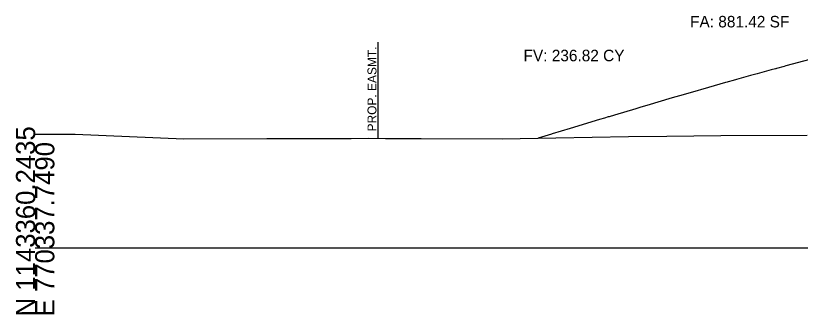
# Model space of a CAD drawing. Extents: x -26 to 5403, y -13 to 9553.
# Drawn here: x 3997.2 to 4111.7, y 1990.3 to 2033.8 of the extents above; entities that cross this region are included whole.
import ezdxf

# ---------------------------------------------------------------- set-up
doc = ezdxf.new("R2010")
doc.units = 0
for name, color, linetype in [('Draft_XS_Grid', 7, 'Continuous'), ('DTM_X_GROUND', 7, 'Continuous'), ('ROW_EASEMENTS', 7, 'Continuous'), ('SLOPE_STAKES_FILL', 7, 'Continuous'), ('XS_CELL', 7, 'Continuous'), ('XS_M_SHAPES_EARTHWORK', 7, 'Continuous'), ('XS_P_GROUND', 7, 'Continuous'), ('XS_SHEET_EW_TX_AREA', 7, 'Continuous'), ('XS_SHEET_EW_TX_VOLUME', 7, 'Continuous')]:
    doc.layers.add(name, color=color, linetype=linetype)

msp = doc.modelspace()

# ---------------------------------------------------------------- linework, layer by layer
at = {"layer": 'DTM_X_GROUND'}
msp.add_lwpolyline([(4000, 2016.56), (4005.83, 2016.53), (4021.71, 2015.84), (4033.8, 2015.93), (4036.66, 2015.9), (4046.12, 2015.93), (4048.71, 2015.94), (4051.11, 2015.93), (4056.33, 2015.92), (4068.17, 2015.87), (4075.98, 2015.99), (4086.57, 2016.19), (4092.16, 2016.23), (4100.06, 2016.35), (4112.65, 2016.39)], dxfattribs=at)
at = {"layer": 'ROW_EASEMENTS'}
msp.add_line((4050, 2029.94), (4050, 2015.94), dxfattribs=at)
at = {"layer": 'XS_CELL'}
msp.add_line((4000, 2000), (4200, 2000), dxfattribs=at)
at = {"layer": 'XS_M_SHAPES_EARTHWORK'}
msp.add_lwpolyline([(4113.03, 2027.41), (4109.54, 2026.48), (4109.28, 2026.41), (4108.2, 2026.11), (4108.07, 2026.08), (4108.03, 2026.07), (4107.38, 2025.9), (4105.37, 2025.34), (4104.39, 2025.07), (4102.35, 2024.5), (4101.87, 2024.37), (4101.14, 2024.17), (4100.98, 2024.12), (4100.76, 2024.06), (4098.28, 2023.36), (4095.59, 2022.58), (4094.04, 2022.14), (4092.96, 2021.82), (4090.85, 2021.21), (4089.76, 2020.88), (4088.24, 2020.43), (4087.64, 2020.25), (4084.56, 2019.33), (4083.75, 2019.09), (4083.63, 2019.05), (4083.09, 2018.89), (4082.33, 2018.66), (4078.07, 2017.38), (4075.46, 2016.59), (4075.36, 2016.56), (4073.39, 2015.95), (4075.98, 2015.99), (4086.57, 2016.19), (4092.16, 2016.23), (4100.06, 2016.35), (4112.65, 2016.39)], dxfattribs=at)
at = {"layer": 'XS_P_GROUND'}
msp.add_lwpolyline([(4113.03, 2027.41), (4109.54, 2026.48), (4109.28, 2026.41), (4108.2, 2026.11), (4108.07, 2026.08), (4108.03, 2026.07), (4107.38, 2025.9), (4105.37, 2025.34), (4104.39, 2025.07), (4102.35, 2024.5), (4101.87, 2024.37), (4101.14, 2024.17), (4100.98, 2024.12), (4100.76, 2024.06), (4098.28, 2023.36), (4095.59, 2022.58), (4094.04, 2022.14), (4092.96, 2021.82), (4090.85, 2021.21), (4089.76, 2020.88), (4088.24, 2020.43), (4087.64, 2020.25), (4084.56, 2019.33), (4083.75, 2019.09), (4083.63, 2019.05), (4083.09, 2018.89), (4082.33, 2018.66), (4078.07, 2017.38), (4075.46, 2016.59), (4075.36, 2016.56), (4073.39, 2015.95)], dxfattribs=at)

# ---------------------------------------------------------------- texts
at = {"layer": 'Draft_XS_Grid'}
msp.add_text('-', height=0.0001, dxfattribs=at).set_placement((4000, 2000))
at = {"layer": 'ROW_EASEMENTS'}
msp.add_text('PROP. EASMT.', height=1.3, rotation=90, dxfattribs=at).set_placement((4049.8, 2016.94))
at = {"layer": 'SLOPE_STAKES_FILL'}
msp.add_text('X', height=0.012, dxfattribs=at).set_placement((4073.39, 2015.95))
at = {"layer": 'XS_CELL'}
for s, p in [('N 1143360.2435', (4000, 1990)), ('E 770337.7490', (4002.8, 1990))]:
    msp.add_text(s, height=2.8, rotation=90, dxfattribs=at).set_placement(p)
at = {"layer": 'XS_SHEET_EW_TX_AREA'}
msp.add_text('FA: 881.42 SF', height=1.68, dxfattribs=at).set_placement((4095.57, 2032.09))
at = {"layer": 'XS_SHEET_EW_TX_VOLUME'}
msp.add_text('FV: 236.82 CY', height=1.68, dxfattribs=at).set_placement((4071.27, 2027.16))

doc.saveas('drawing.dxf')
